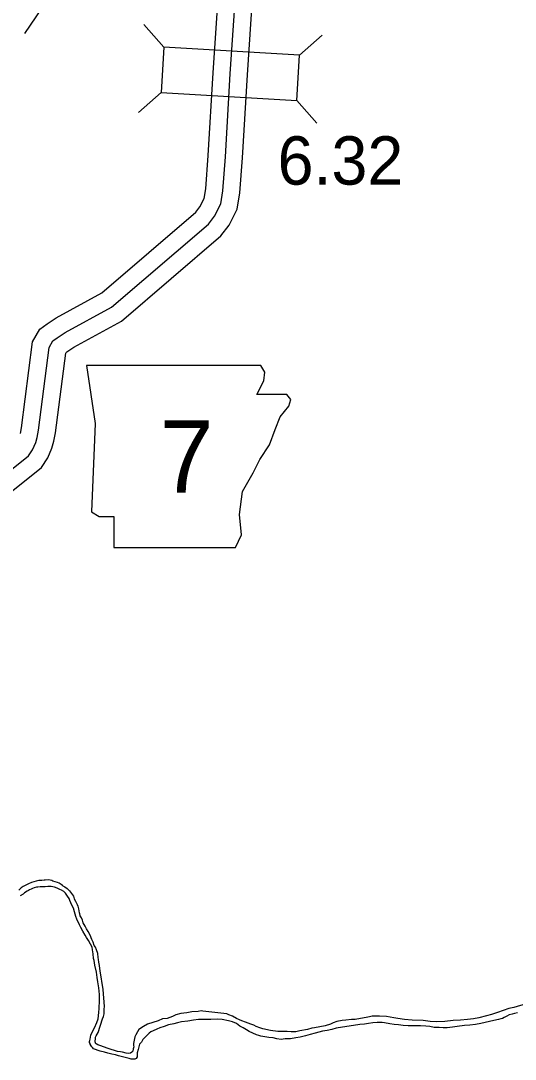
# Model space of a CAD drawing. Extents: x 31699 to 244310, y -8841 to 11474.
# Drawn here: x 96161 to 96449, y 1416 to 2021 of the extents above; entities that cross this region are included whole.
import ezdxf

# ---------------------------------------------------------------- set-up
doc = ezdxf.new("R2010")
doc.units = 0
for name, color, linetype in [('B_Logo', 7, 'Continuous'), ('G-ANNO-TEXT', 7, 'Continuous'), ('R_Draft', 7, 'Continuous'), ('R_XS_EARTHWORK_STAGE1', 7, 'Continuous'), ('R_XS_EARTHWORK_STAGE2', 7, 'Continuous'), ('S_WALL', 7, 'Continuous')]:
    doc.layers.add(name, color=color, linetype=linetype)

msp = doc.modelspace()

# ---------------------------------------------------------------- linework, layer by layer
at = {"layer": 'B_Logo'}
msp.add_lwpolyline([(96106.69, 1720.46), (96165.93, 1767.77), (96168.31, 1771.31), (96170.07, 1775.44), (96170.93, 1778.47), (96171.63, 1782.57), (96177.91, 1830.74), (96180.14, 1834.61), (96182.57, 1836.41), (96187.23, 1839.47), (96214.33, 1854.34), (96270.68, 1902.58), (96274.23, 1907.29), (96277.92, 1914.4), (96279.13, 1921.99), (96280.58, 1941.82), (96283.45, 1990.11), (96288.58, 2066.15)], dxfattribs=at)
at = {"layer": 'G-ANNO-TEXT'}
msp.add_lwpolyline([(96199.74, 1820.32), (96204.81, 1786.49), (96202.56, 1735.17), (96207.07, 1732.35), (96215.53, 1732.35), (96215.53, 1714.3), (96286.58, 1714.3), (96289.97, 1721.64), (96288.84, 1733.48), (96290.53, 1747.01), (96296.73, 1757.73), (96300.68, 1765.62), (96306.32, 1774.08), (96309.7, 1783.1), (96312.52, 1790.44), (96317.6, 1796.64), (96318.73, 1800.59), (96316.47, 1803.41), (96298.99, 1803.41), (96302.94, 1811.3), (96303.5, 1816.38), (96301.16, 1820.27)], close=True, dxfattribs=at)
at = {"layer": 'R_Draft'}
for points in [[(96180.04, 1520.22), (96179.56, 1520.47), (96177.62, 1520.83), (96175.69, 1520.71), (96175.02, 1520.69), (96173.69, 1520.59), (96171.89, 1520.48), (96170.44, 1520.18), (96168.98, 1519.74), (96167.65, 1519.44), (96165.81, 1518.65), (96163.9, 1517.67), (96162.78, 1517.11), (96161.67, 1516.21), (96160.23, 1514.97)], [(96185.98, 1517.49), (96185.77, 1517.62), (96184.88, 1518.27), (96183.8, 1518.98), (96182.72, 1519.35), (96181.45, 1519.79), (96180.04, 1520.22)], [(96185.98, 1517.49), (96187.03, 1516.9), (96188.35, 1515.82), (96189.79, 1514.44), (96190.99, 1512.94), (96192.07, 1511.44), (96192.55, 1509.82), (96193.27, 1508.44), (96194.17, 1506.58), (96194.59, 1505.5), (96194.95, 1504.12), (96195.44, 1501.76)], [(96207.55, 1421.2), (96203.85, 1422.58), (96203.3, 1423.17), (96202.75, 1423.69), (96202.34, 1424.28), (96201.91, 1425.27), (96201.77, 1425.67), (96201.49, 1426.27), (96201.48, 1426.73), (96201.66, 1427.34), (96201.91, 1428.15), (96202.08, 1429.36), (96202.25, 1430.5), (96203.01, 1432.26), (96204.28, 1434.76), (96205.67, 1437.81), (96206.42, 1439.97), (96206.93, 1443.59), (96207.07, 1446), (96207.22, 1450.75), (96207.2, 1454.1), (96206.84, 1457.97), (96206.35, 1461.57), (96205.89, 1464.03), (96205.42, 1467.09), (96204.58, 1471.22), (96204.05, 1473.95), (96203.75, 1475.08), (96203.62, 1477.88), (96203.23, 1480.15), (96202.92, 1481.68), (96201.94, 1483.52), (96200.82, 1485.64), (96199.65, 1487.35), (96198.88, 1488.66), (96197.49, 1491.04), (96196.44, 1493.22), (96195.6, 1494.67), (96194.12, 1497.97), (96193.55, 1499.56), (96192.68, 1502.28), (96192.03, 1504.34), (96191.05, 1506.12), (96189.98, 1508.9), (96189.49, 1510.09), (96188.66, 1511.34), (96187.41, 1513.18), (96186.39, 1514.03), (96185.1, 1514.86), (96184.23, 1515.24), (96182.61, 1516), (96180.99, 1516.57), (96179.18, 1517.12), (96177.11, 1517), (96175.59, 1516.83), (96174.18, 1516.86), (96172.65, 1516.89), (96171.32, 1516.65), (96170.59, 1516.57), (96169.13, 1516.2), (96168.27, 1515.91), (96167.42, 1515.55), (96166.43, 1515.06), (96165.84, 1514.64), (96165.05, 1514.36), (96163.54, 1513.25), (96162.82, 1512.56), (96160.98, 1511.58)], [(96316.68, 1432.53), (96311.15, 1432.66), (96306.93, 1433.15), (96302.51, 1434.11), (96300.69, 1434.8), (96298.54, 1435.62), (96297.12, 1436.25), (96295.44, 1436.87), (96292.41, 1438), (96290.12, 1438.81), (96288.91, 1439.32), (96287.02, 1440.21), (96284.79, 1441.49), (96282.64, 1442.37), (96281.36, 1442.94), (96267.38, 1444.52), (96266.51, 1444.57), (96264.79, 1444.26), (96260.99, 1444.09), (96258.21, 1443.42), (96254.68, 1443.06), (96251.64, 1442.25), (96249.72, 1441.33), (96246.62, 1440.25), (96244.03, 1439.92), (96241.45, 1438.85), (96235.3, 1436.95), (96232.93, 1435.62), (96230.17, 1433.82), (96229.41, 1432.52), (96228.38, 1430.69), (96227.81, 1429.54), (96227.11, 1425.65), (96227.14, 1424.51), (96227.22, 1423.78), (96226.85, 1422.56), (96226.62, 1421.22), (96226.1, 1420.67), (96225.31, 1420.05), (96223.92, 1419.75), (96222.78, 1419.92), (96220.57, 1420.6), (96219.56, 1420.77), (96217.82, 1421), (96212.25, 1422.73), (96207.47, 1424.48), (96206.26, 1424.92), (96205.31, 1425.43), (96205.18, 1425.49), (96204.83, 1426.08), (96204.68, 1426.61), (96204.75, 1426.75), (96204.73, 1427.49), (96204.85, 1428.02), (96204.95, 1429.23), (96205.4, 1430.04), (96206.41, 1432.08), (96209.02, 1440.03), (96209.58, 1441.38), (96209.95, 1442.87), (96210.05, 1444.14), (96209.95, 1445.54), (96210.11, 1447.22), (96209.46, 1457.1), (96207.73, 1467.89), (96207.5, 1469.29), (96207.32, 1470.95), (96206.81, 1472.95), (96206.63, 1474.55), (96206.47, 1475.75), (96206.22, 1477.95), (96205.43, 1480.14), (96204.92, 1481.66), (96204.23, 1482.71), (96203.58, 1484.7), (96202.88, 1486.16), (96201.75, 1488.67), (96200.56, 1490.85), (96199.66, 1492.36), (96198.89, 1493.88), (96197.77, 1495.86), (96197.27, 1497.38), (96196.7, 1498.77), (96196.07, 1500.03), (96195.71, 1501.22), (96195.44, 1501.76)], [(96461.13, 1450.24), (96448.62, 1446.64), (96445.7, 1445.97), (96442.4, 1444.82), (96439.09, 1443.66), (96435.58, 1442.5), (96432.74, 1441.69), (96428.23, 1440.58), (96425.18, 1439.96), (96421.65, 1439.67), (96417.66, 1439.17), (96413.34, 1439), (96408.41, 1438.47), (96403.75, 1438.28), (96399.88, 1438.39), (96395.93, 1439.09), (96389.53, 1439.26), (96384.98, 1439.61), (96381.1, 1440.25), (96378.69, 1440.66), (96374.54, 1441.29), (96370.33, 1441.58), (96366.13, 1441.48), (96364.61, 1441.17), (96362.69, 1440.72), (96359.36, 1440.23), (96356.18, 1439.69), (96354.11, 1439.63), (96350.79, 1439.28), (96348.59, 1438.96), (96345.54, 1438.35), (96343.49, 1437.63), (96341.91, 1436.92), (96338.73, 1435.97), (96332.56, 1434.81), (96331.04, 1434.5), (96328.39, 1433.83), (96324.01, 1432.92), (96321.62, 1432.46), (96318.89, 1432.39), (96316.68, 1432.53)], [(96441.11, 1439.97), (96439.79, 1439.6), (96437.01, 1438.93), (96429.45, 1437.2), (96426.39, 1436.72), (96423, 1436.36), (96419.87, 1436.08), (96415.75, 1435.51), (96413.03, 1435.11), (96409.84, 1434.76), (96407.51, 1434.7), (96405.24, 1434.91), (96402.3, 1435.04), (96399.82, 1435.51), (96397.41, 1435.78), (96394.28, 1435.9), (96392.27, 1435.99), (96390.01, 1435.93), (96387.14, 1435.99), (96384.2, 1436.18), (96381.46, 1436.52), (96378.92, 1436.72), (96376.38, 1437.12), (96373.36, 1437.71), (96371.89, 1437.88), (96369.09, 1437.81), (96366.56, 1437.61), (96364.04, 1437.28), (96361.58, 1436.88), (96358.99, 1436.61), (96345.24, 1434.53), (96342.59, 1433.86), (96339.87, 1433.25), (96337.15, 1432.72), (96332.9, 1431.74), (96329.92, 1430.93), (96327.34, 1430.19), (96324.16, 1429.31), (96321.57, 1428.91), (96318.45, 1428.36), (96315.52, 1428.36), (96313.13, 1428.03), (96310.52, 1428.43), (96308.44, 1428.98), (96305.97, 1429.05), (96303.55, 1429.59), (96301.34, 1430), (96300, 1430.24), (96298.79, 1430.67), (96294.48, 1432.7), (96292.99, 1433.6), (96291.03, 1434.69), (96289.07, 1435.78), (96287.03, 1437.2), (96284.74, 1438.21), (96282.39, 1438.82), (96278.64, 1439.59), (96276.1, 1439.79), (96272.03, 1439.69), (96269.04, 1439.62), (96264.84, 1439.58), (96261.98, 1439.17), (96258.72, 1438.69), (96254.94, 1438.19), (96252.62, 1437.66), (96250.56, 1437.14), (96247.38, 1436.46), (96244.87, 1435.59), (96242.49, 1434.73), (96240.7, 1434.02), (96238.46, 1432.96), (96237.14, 1432.39), (96236.23, 1431.69), (96235.38, 1430.8), (96234.73, 1430.12), (96232.58, 1428.06), (96231.69, 1426.5), (96230.65, 1425.2), (96230.09, 1423.65), (96229.8, 1422.1), (96229.18, 1420.21), (96229.28, 1418.74), (96229.17, 1417.87), (96228.59, 1416.86), (96227.87, 1416.57), (96227, 1416.48), (96225.73, 1416.52), (96224.59, 1416.82), (96218.35, 1418.53), (96216.54, 1419.02), (96214.46, 1419.44), (96212.11, 1419.98), (96210.1, 1420.6), (96207.55, 1421.2)], [(96450.9, 1443.43), (96448.97, 1443.04), (96447.72, 1442.68), (96445.92, 1442.3), (96444.54, 1441.59), (96442.96, 1440.68), (96442.04, 1440.19), (96441.11, 1439.97)]]:
    msp.add_lwpolyline(points, dxfattribs=at)
at = {"layer": 'R_XS_EARTHWORK_STAGE1'}
for p, q in [((96173.42, 2028.08), (96163.53, 2013.52)), ((96244.71, 2005.64), (96233.02, 2018.81)), ((96323.77, 2000.94), (96336.93, 2012.62)), ((96243.14, 1979.29), (96229.98, 1967.61)), ((96322.2, 1974.58), (96333.88, 1961.42))]:
    msp.add_line(p, q, dxfattribs=at)
msp.add_lwpolyline([(96243.14, 1979.29), (96322.2, 1974.58), (96323.77, 2000.94), (96244.71, 2005.64)], close=True, dxfattribs=at)
at = {"layer": 'R_XS_EARTHWORK_STAGE2'}
for points in [[(96112.94, 1712.66), (96173.37, 1760.92), (96177.13, 1766.51), (96179.52, 1772.09), (96180.7, 1776.26), (96181.52, 1781.08), (96187.56, 1827.47), (96187.77, 1827.82), (96188.3, 1828.21), (96192.38, 1830.9), (96220.05, 1846.07), (96278.01, 1895.69), (96282.72, 1901.93), (96287.54, 1911.23), (96289.08, 1920.83), (96290.56, 1941.16), (96293.43, 1989.48), (96298.62, 2066.42)], [(96161.16, 1780.68), (96161.74, 1784.05), (96168.25, 1834.02), (96172.52, 1841.41), (96176.83, 1844.61), (96182.07, 1848.05), (96208.61, 1862.61), (96263.35, 1909.47), (96265.74, 1912.64), (96268.3, 1917.57), (96269.19, 1923.14), (96270.6, 1942.48), (96273.47, 1990.75), (96278.54, 2065.88)]]:
    msp.add_lwpolyline(points, dxfattribs=at)

# ---------------------------------------------------------------- texts
at = {"layer": 'G-ANNO-TEXT'}
msp.add_text('7', height=42.24, dxfattribs=at).set_placement((96242.28, 1746.19))
at = {"layer": 'S_WALL'}
msp.add_text('6.32', height=28.16, dxfattribs=at).set_placement((96311, 1925.58))

doc.saveas('drawing.dxf')
